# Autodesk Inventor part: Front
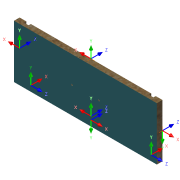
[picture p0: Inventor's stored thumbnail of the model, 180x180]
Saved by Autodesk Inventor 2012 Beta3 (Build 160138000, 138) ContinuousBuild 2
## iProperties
Created: 2011-02
Part Number: Front
Material: Default
Document SubType Name: Modeling
Designer: Beta-8540w
Density: 1 g/cm^3
back_width: 13.421 in
drawer_width: 16.000 in
edge_band_thickness: 0.039 in
drawer_height: 6.000 in
drawer_depth: 16.000 in
drawer_side_height: 5.000 in
bottom_thickness: 0.130 in
Author: Beta-8540w
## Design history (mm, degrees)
sketch "Sketch1"
  geometry: L1 (-202.2, -75.2)-(202.2, -75.2); L2 (202.2, -75.2)-(202.2, 75.2); L3 (202.2, 75.2)-(-202.2, 75.2); L4 (-202.2, 75.2)-(-202.2, -75.2); 3 further points
  constraints: 8 end point, 2 midpoint, 2 parallel, 1 horizontal, 1 horizontal alignment, 1 perpendicular, 1 vertical alignment
  dimensions: "drwr_core_width" = 404.4 distance of L3.end L2.end (= drawer_width - 2 x edge_band_thickness); "drwr_core_height" = 150.4 distance of L2.end L1.end (= drawer_height - 2 x edge_band_thickness)
extrude "Drawer Face" new body sketch "Sketch1" distance "d2" = 15.875; taper "d3" = 0 deg
sketch "Sketch2"
  geometry: 1 further point
hole "Single Hole Pull" sketch "Sketch2" at (0, 0) diameter "d4" = 4.4958; stored, may be unused: countersink angle "d8" = 82 deg, drill point angle "d10" = 118 deg; dims "d5" = 19.05, "d6" = 8.4328, "d7" = 6.35, "d9" = 25.4
sketch "Sketch3"
  geometry: L1 (-38.1, 0)-(38.1, 0); 2 further points
  constraints: 2 end point, 1 coincident, 1 horizontal, 1 midpoint
  dimensions: "dbl_pull_width" = 76.2 distance of L1.start L1.end
hole "Double Hole Pull" sketch "Sketch3" at (-38.1, 0), (38.1, 0) diameter "d12" = 4.4958; stored, may be unused: countersink angle "d16" = 82 deg, drill point angle "d18" = 118 deg; dims "d13" = 19.05, "d14" = 8.4328, "d15" = 6.35, "d17" = 25.4
sketch "Sketch4"
  geometry: L1 (202.2, -75.2)-(-202.2, -75.2) reference; L2 (202.2, 75.2)-(202.2, -75.2) reference; L3 (-202.2, 75.2)-(202.2, 75.2) reference; L4 (-202.2, -75.2)-(-202.2, 75.2) reference; L5 (-183.15, 75.2)-(-170.45, 75.2); L6 (-170.45, 75.2)-(-170.45, -75.2); L7 (-170.45, -75.2)-(-183.15, -75.2); L8 (-183.15, -75.2)-(-183.15, 75.2); L9 (183.15, 75.2)-(170.45, 75.2); L10 (170.45, 75.2)-(170.45, -75.2); L11 (170.45, -75.2)-(183.15, -75.2); L12 (183.15, -75.2)-(183.15, 75.2); 1 further point
  constraints: 16 end point, 4 parallel, 4 point on line, 2 horizontal, 2 perpendicular, 1 collinear
  dimensions: "d19" = 12.7 distance of L5.start L5.end; "d20" = 19.05 distance between parallel lines of L8 L4; "d21" = 19.05 distance between parallel lines of L2 L12 (= d20); "back_width" = 340.9 distance between parallel lines of L10 L6 (derived)
extrude "Side Relief" cut sketch "Sketch4" distance "d22" = 6.35; taper "d23" = 0 deg
sketch "Sketch5"
  geometry: L1 (170.45, -75.2)-(170.45, 75.2) reference; L2 (-170.45, 75.2)-(-170.45, -75.2) reference; L3 (170.45, -75.2)-(-170.45, -75.2) reference; L4 (-170.45, -65.548)-(170.45, -65.548); L5 (170.45, -65.548)-(170.45, -62.246); L6 (170.45, -62.246)-(-170.45, -62.246); L7 (-170.45, -62.246)-(-170.45, -65.548); 1 further point
  constraints: 8 end point, 2 parallel, 2 point on line, 1 horizontal, 1 perpendicular
  dimensions: "d24" = 9.652 distance between parallel lines of L3 L4; "bottom_thickness" = 3.302 distance of L4.end L5.end
extrude "Bottom Relief" cut sketch "Sketch5" distance "d26" = 6.35; taper "d27" = 0 deg
body "Solid1"
other parameters: "d28" = 0, "d29" = 0, "d30" = 0, "d31" = 0, "d32" = 0, "d33" = 180 deg, "d34" = 0, "d35" = 0, "d36" = 0, "d37" = 0, "d38" = 180 deg, "d39" = 0, "d40" = 0, "d41" = 0, "d42" = 0, "d43" = 0, "d44" = 180 deg, "d45" = 180 deg, "d46" = 0, "d47" = 0, "d48" = 0, "d49" = 0, "d50" = 180 deg, "d51" = 0, "d52" = 0, "d53" = 0, "d54" = 0, "d55" = 0, "d56" = 180 deg, "d57" = 0, "d58" = 0, "d59" = 0, "d60" = 0, "d61" = 0, "d62" = 90 deg, "d63" = 0, "d64" = 0, "d65" = 0, "d66" = 0, "d67" = 0, "d68" = -90 deg, "d69" = 0, "drawer_width" = 406.4 [user parameter; used in 1 equation term], "edge_band_thickness" = 1 [user parameter; used in 2 equation terms], "drawer_height" = 152.4 [user parameter; used in 2 equation terms], "drawer_depth" = 406.4 [user parameter], "drawer_side_height" = 127 (computed from drawer_height) [user parameter]
